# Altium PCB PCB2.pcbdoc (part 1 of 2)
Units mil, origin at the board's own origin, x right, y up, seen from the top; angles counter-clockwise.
Board outline 7114.17 x 3886.41 mil, 4 copper layers (Top Layer, Inner1, Inner2, Bottom Layer); 197 components, 125 nets, 754 pads, 711 vias.
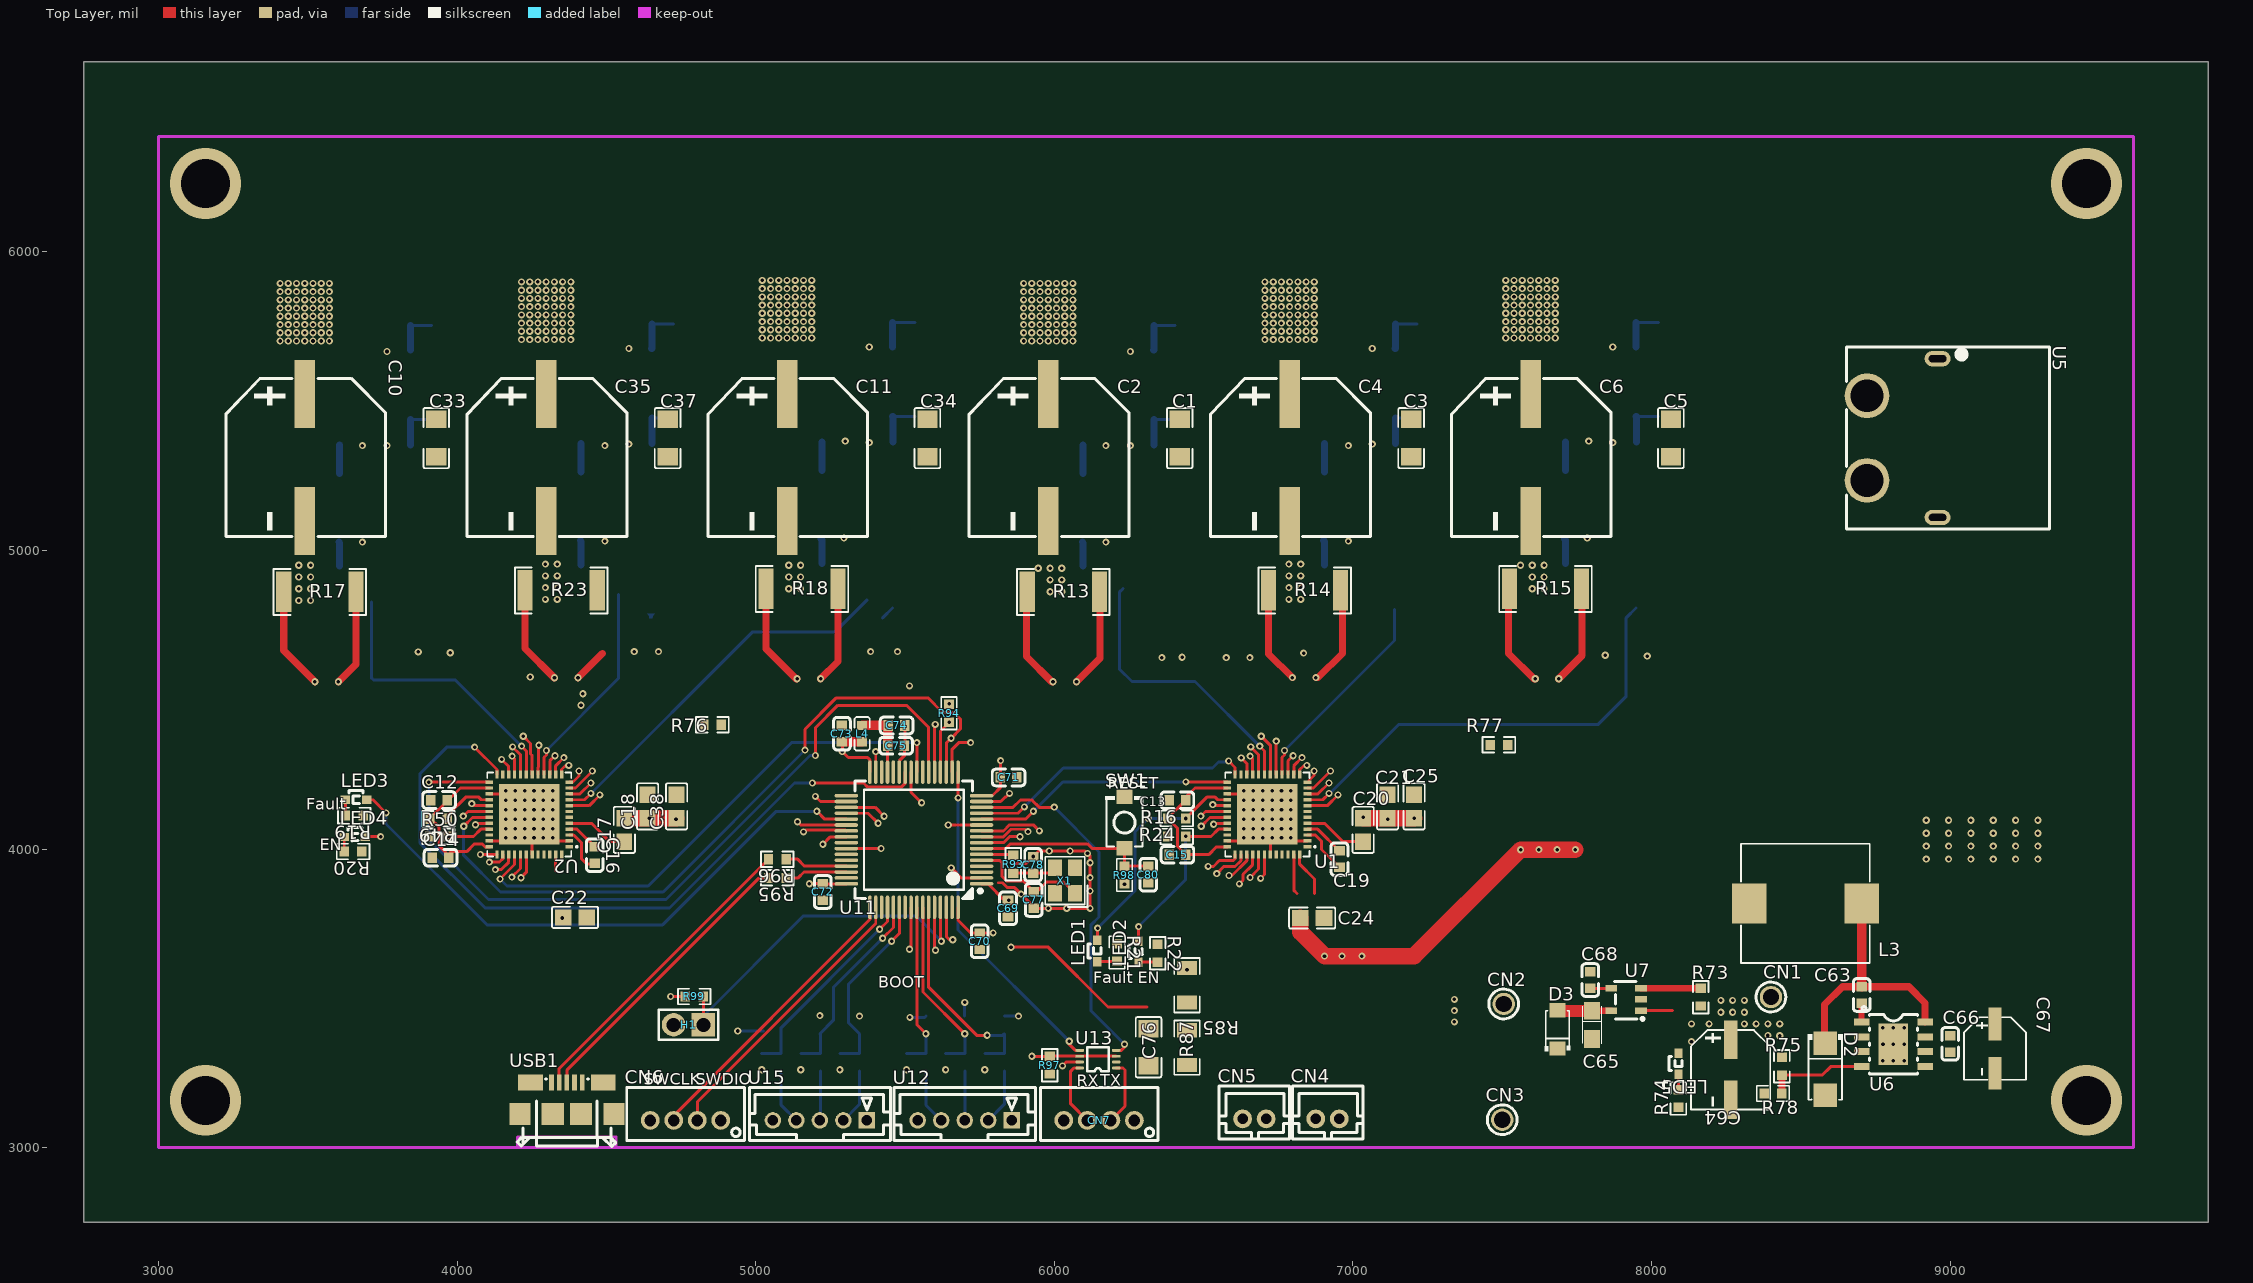
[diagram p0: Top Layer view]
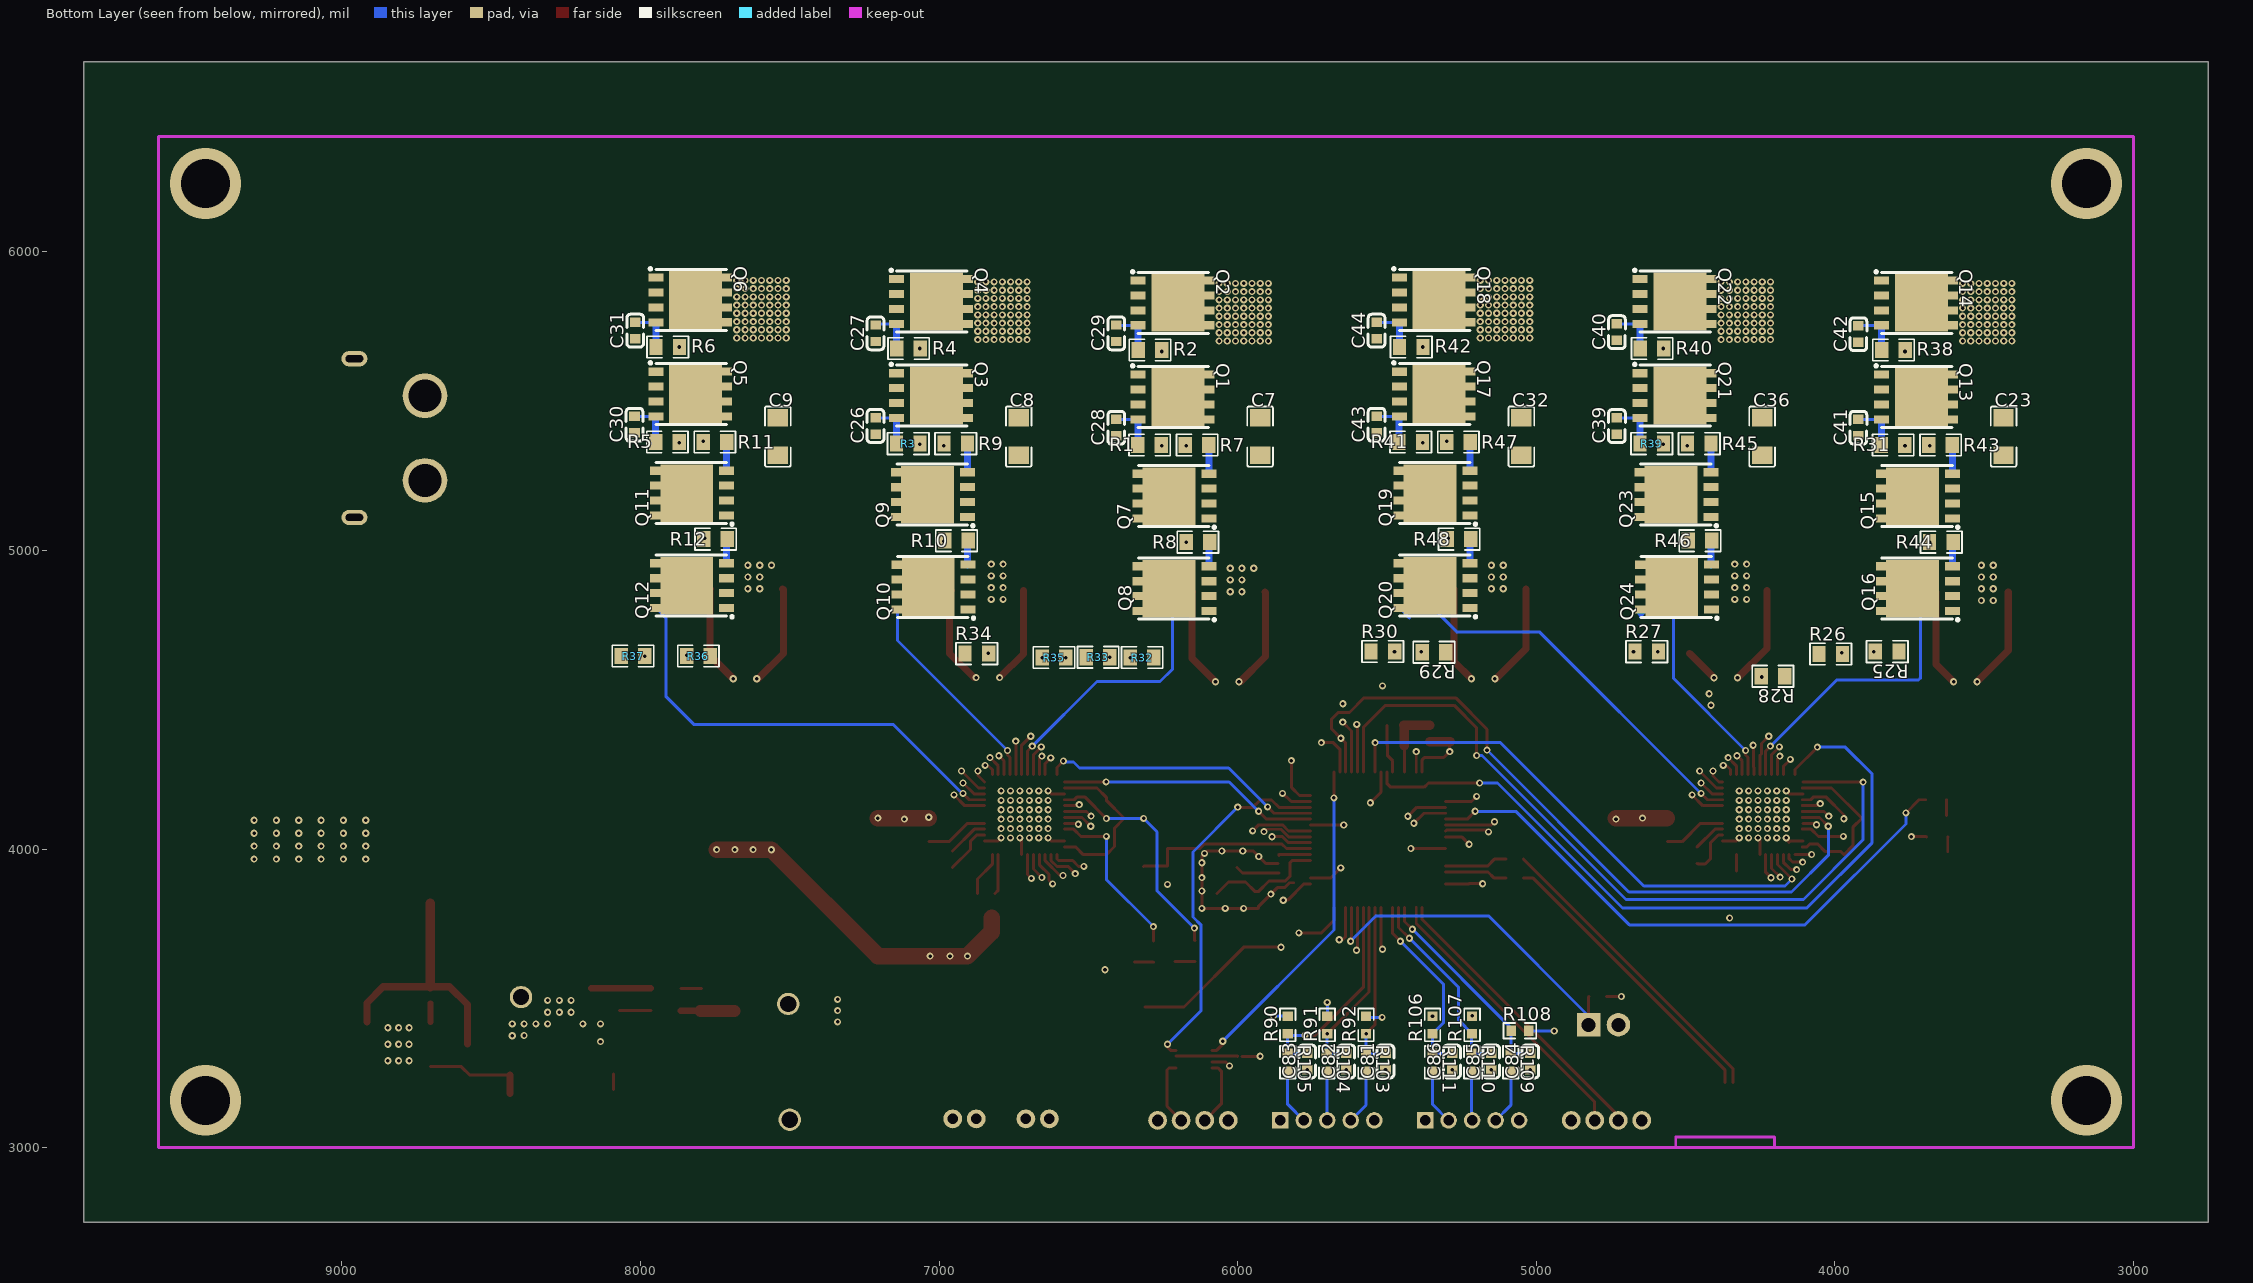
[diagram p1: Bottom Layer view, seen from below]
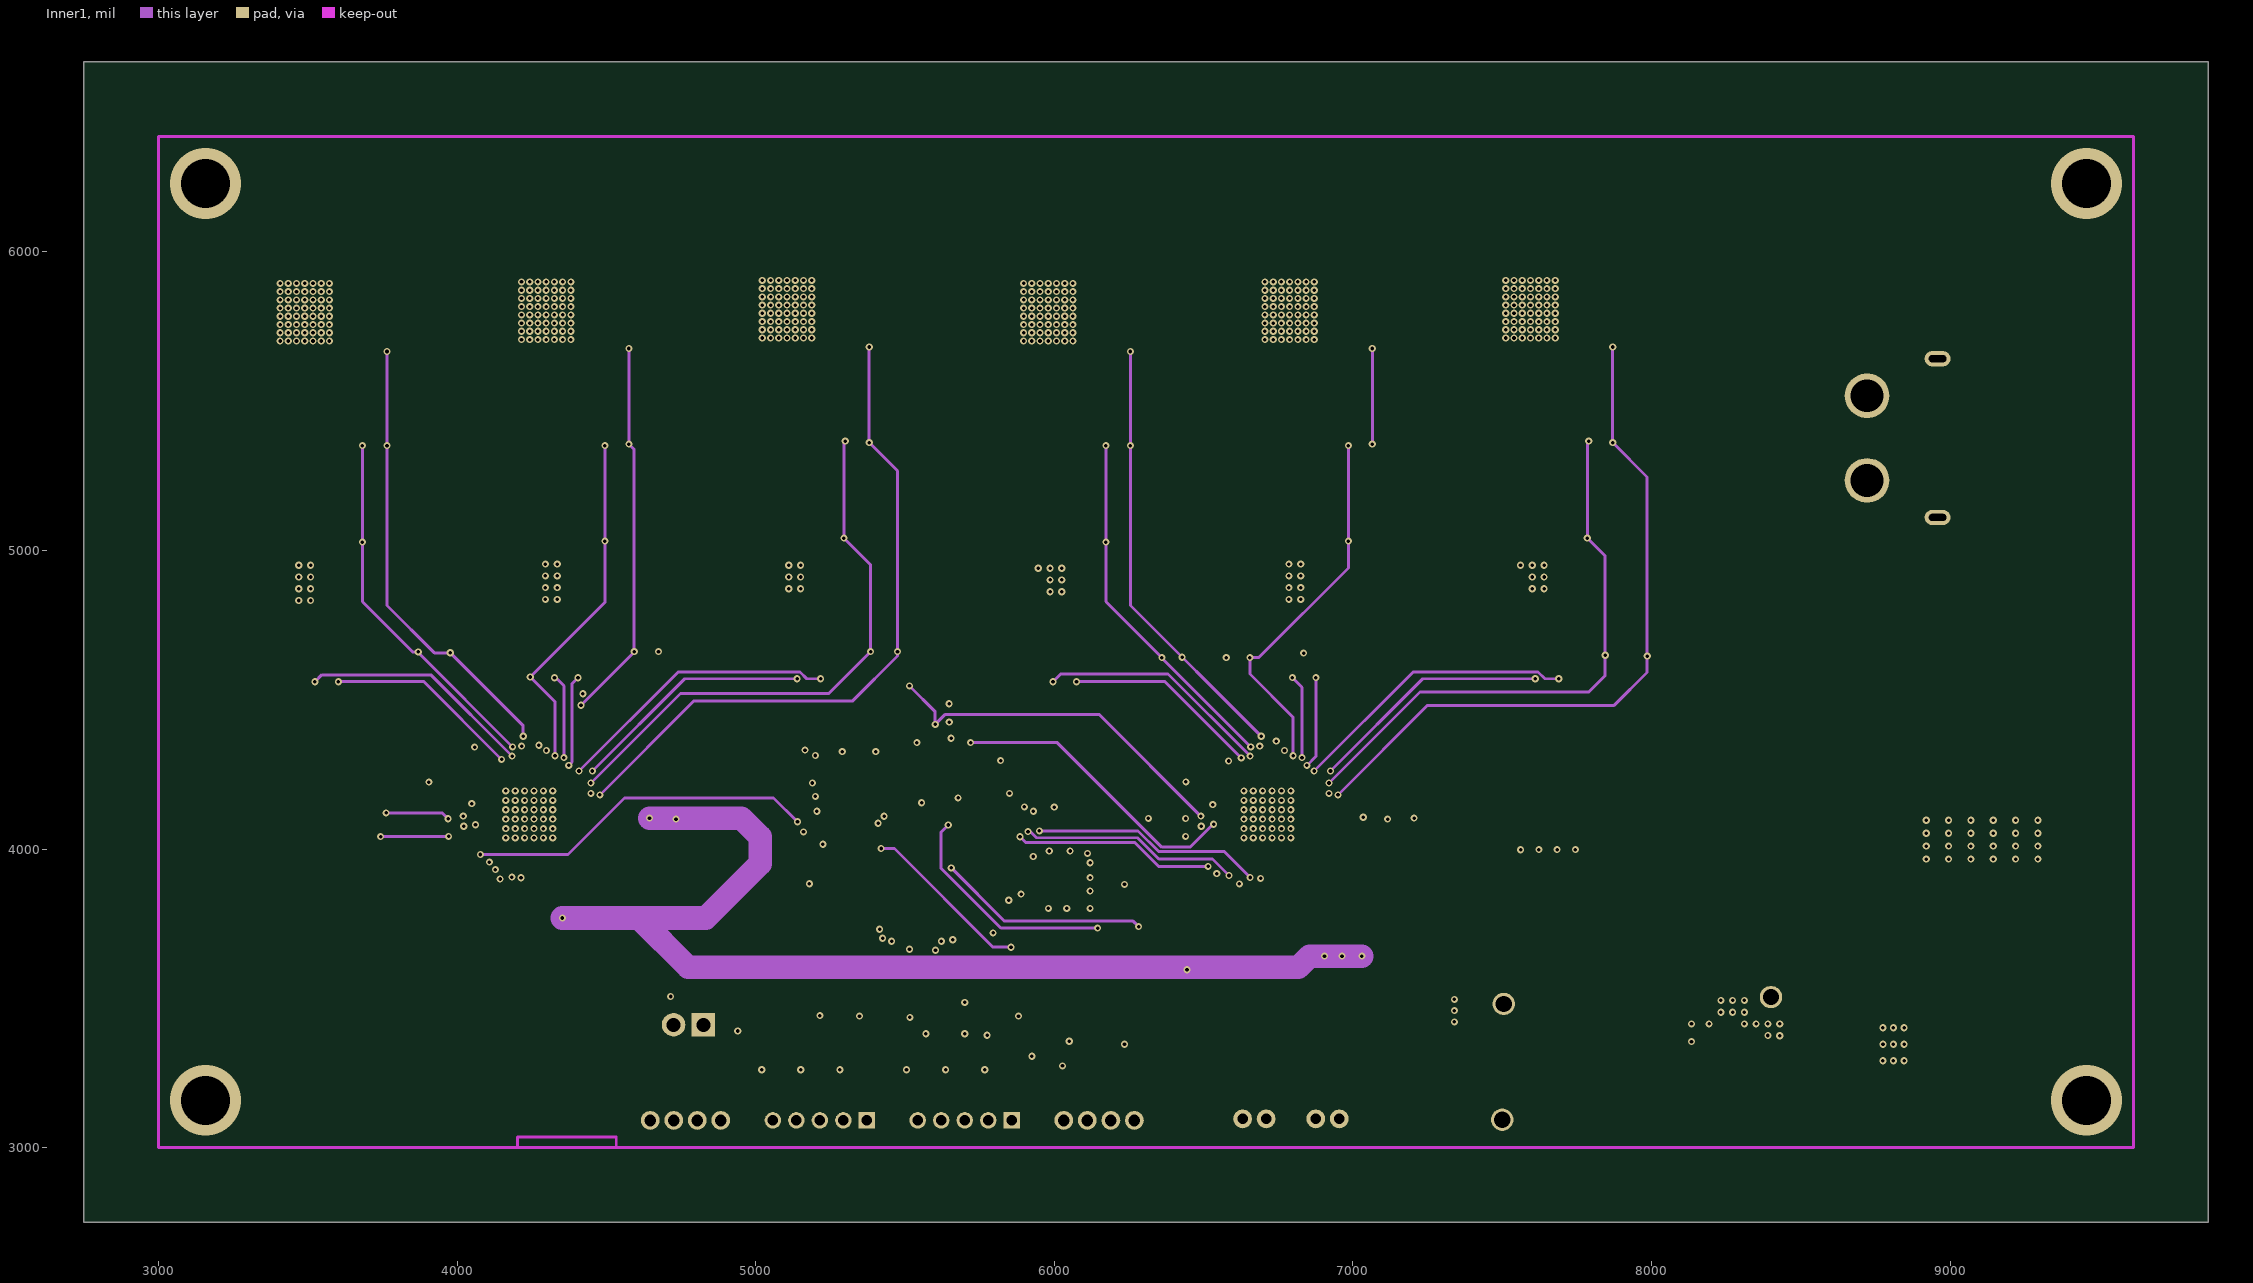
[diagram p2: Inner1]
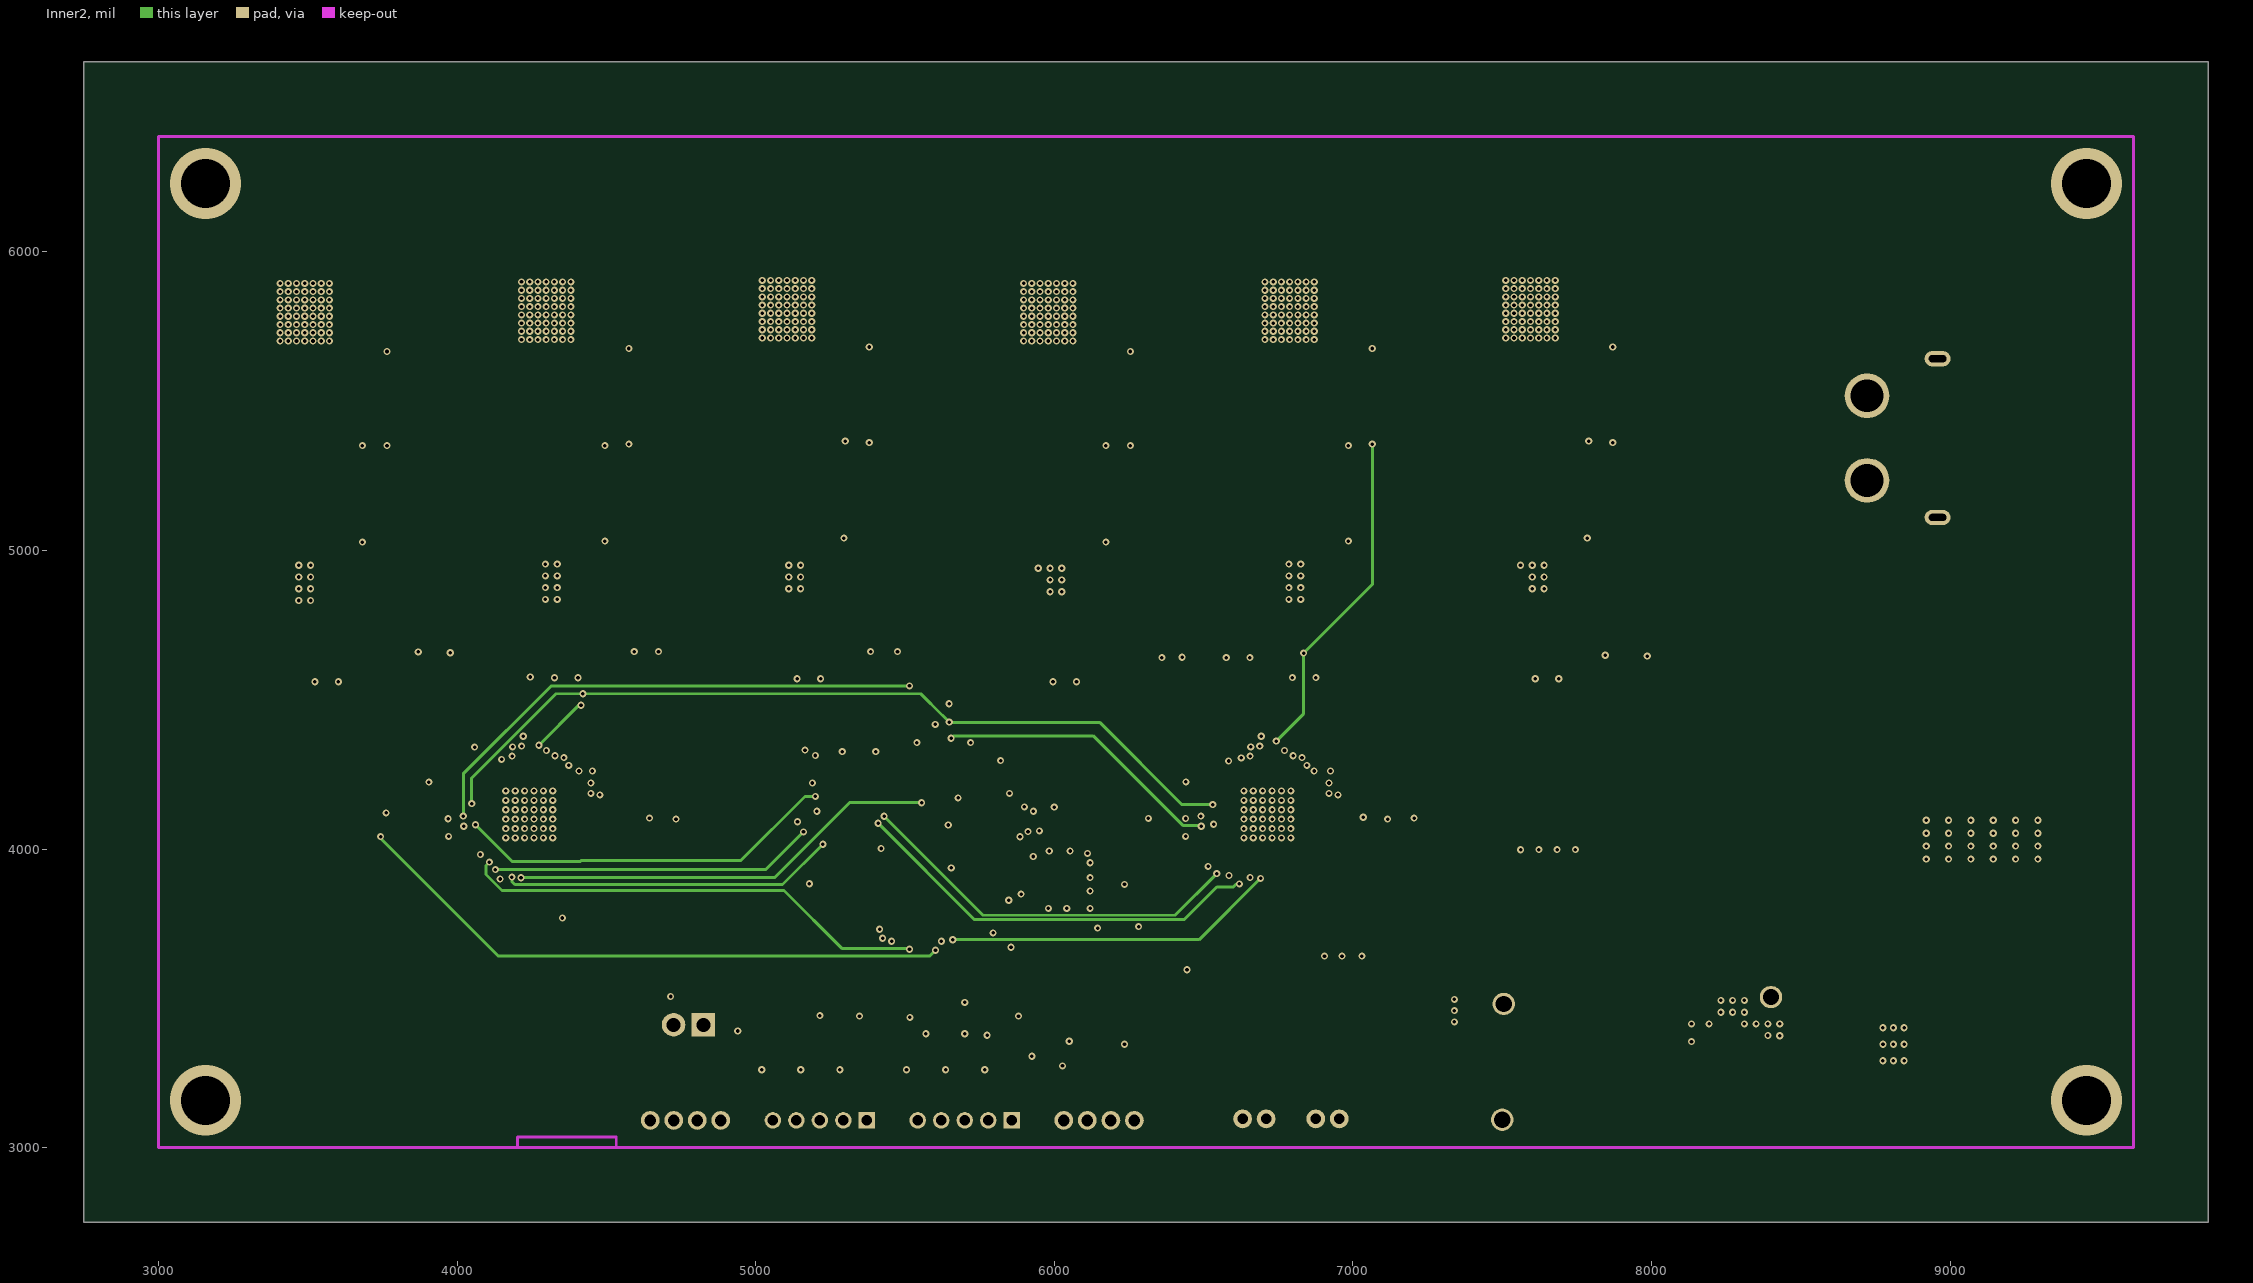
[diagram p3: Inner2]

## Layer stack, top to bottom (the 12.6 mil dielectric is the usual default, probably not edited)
Top Layer: signal copper (thickness not stored)
Dielectric: dielectric 12.6, FR-4, Dk 4.8
Inner1: signal copper (thickness not stored)
Dielectric: dielectric 12.6, FR-4, Dk 4.8
Inner2: signal copper (thickness not stored)
Dielectric: dielectric 12.6, FR-4, Dk 4.8
Bottom Layer: signal copper (thickness not stored)

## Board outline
9864.17,2750 2750,2750 2750,6636.41 9864.17,6636.41

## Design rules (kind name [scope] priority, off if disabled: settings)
BoardOutlineClearance copperThickness1oz [All] p0: genericclearance=10 ignorepadtopadclearanceinfootprint=FALSE except(0: Arc-SplitContinuation Track-SplitContinuation SMDPad-SplitContinuation THPad-SplitContinuation Via-SplitContinuation Fill-SplitContinuation Poly-SplitContinuation Region-SplitContinuation Text-SplitContinuation; 6: Track-CutoutEdge SMDPad-CutoutEdge THPad-CutoutEdge Via-CutoutEdge Region-CutoutEdge; 11.8: Track-OutlineEdge SMDPad-OutlineEdge THPad-OutlineEdge Via-OutlineEdge Fill-OutlineEdge Region-OutlineEdge Poly-OutlineEdge Text-OutlineEdge Fill-CutoutEdge)
BoardOutlineClearance copperThickness2oz [All] p0: genericclearance=10 ignorepadtopadclearanceinfootprint=FALSE except(0: Arc-SplitContinuation Track-SplitContinuation SMDPad-SplitContinuation THPad-SplitContinuation Via-SplitContinuation Fill-SplitContinuation Poly-SplitContinuation Region-SplitContinuation Text-SplitContinuation; 6: Track-CutoutEdge SMDPad-CutoutEdge THPad-CutoutEdge Via-CutoutEdge Region-CutoutEdge; 11.8: Track-OutlineEdge SMDPad-OutlineEdge THPad-OutlineEdge Via-OutlineEdge Fill-OutlineEdge Region-OutlineEdge Poly-OutlineEdge Text-OutlineEdge Fill-CutoutEdge)
Clearance copperThickness1oz [(InNet('VM') OR InNet('PGND') OR InNet('$1I2936\C_H') OR InNet('$1I2936\A_H') OR InNet('M1_C') OR InNet('M1_A') OR InNet('M1_B') OR InNet('$1I2936\GH_C') OR InNet('$1I2936\GH_B') OR InNet('$1I2936\GH_A') OR InNet('$1I2936\GL_C') OR InNet('$1I2936\GL_B') OR InNet('$1I2936\GL_A') OR InNet('PA0') OR InNet('AGND') OR InNet('PA1') OR InNet('$1I2936\DVDD') OR InNet('5V') OR InNet('$1I2936\B_H') OR InNet('MISO') OR InNet('MOSI') OR InNet('SCK') OR InNet('PA4') OR InNet('PB13') OR InNet('PB14') OR InNet('$1I3034\C_H') OR InNet('$1I3034\B_H') OR InNet('$1I3034\A_H') OR InNet('PC4') OR InNet('PC0') OR InNet('$1I3034\DVDD') OR InNet('$1N561') OR InNet('PH') OR InNet('3.3V') OR InNet('$1N2428') OR InNet('NRST') OR InNet('M2_C') OR InNet('M2_B') OR InNet('M2_A') OR InNet('$1I3034\GH_C') OR InNet('$1I3034\GH_B') OR InNet('$1I3034\GH_A') OR InNet('$1I3034\GL_C') OR InNet('$1I3034\GL_B') OR InNet('$1I3034\GL_A') OR InNet('$1N2597') OR InNet('$1N551') OR InNet('PB4') OR InNet('PB5') OR InNet('PB6') OR InNet('PB7') OR InNet('PB8') OR InNet('PB9') OR InNet('PB12') OR InNet('PC6') OR InNet('PB3') OR InNet('PC7') OR InNet('PB0') OR InNet('PC8') OR InNet('PB1') OR InNet('UART_RX') OR InNet('UART_TX') OR InNet('PA13') OR InNet('PA14') OR InNet('PC12') OR InNet('PC11') OR InNet('PC10') OR InNet('PC2') OR InNet('B2') OR InNet('B1') OR InNet('VDDA') OR InNet('PC1') OR InNet('$1N72792') OR InNet('$1N72949') OR InNet('$1N72945') OR InNet('PB15') OR InNet('PC3') OR InNet('PC13') OR InNet('PB2') OR InNet('$1N77944') OR InNet('$1N77945') OR InNet('D+') OR InNet('D-') OR InNet('$1I2936\$1N44900') OR InNet('$1I2936\$1N44903') OR InNet('$1I2936\$1N44964') OR InNet('$1I2936\$1N44967') OR InNet('$1I2936\$1N44911') OR InNet('$1I2936\$1N44914') OR InNet('$1I2936\$1N44906') OR InNet('$1I2936\$1N44907') OR InNet('$1I2936\$1N44970') OR InNet('$1I2936\$1N44971') OR InNet('$1I2936\$1N44917') OR InNet('$1I2936\$1N44918') OR InNet('$1I2936\$1N44883') OR InNet('$1I2936\$1N44882') OR InNet('$1I2936\$1N44875') OR InNet('$1N87601') OR InNet('$1I3034\$1N44883') OR InNet('$1I3034\$1N44882') OR InNet('$1I3034\$1N44875') OR InNet('$1I3034\$1N44964') OR InNet('$1I3034\$1N44967') OR InNet('$1I3034\$1N44900') OR InNet('$1I3034\$1N44903') OR InNet('$1I3034\$1N44911') OR InNet('$1I3034\$1N44914') OR InNet('$1I2936\$1N44985') OR InNet('$1I2936\$1N44986') OR InNet('$1I3034\$1N44985') OR InNet('$1I3034\$1N44986') OR InNet('$1I3034\$1N44906') OR InNet('$1I3034\$1N44907') OR InNet('$1I3034\$1N44917') OR InNet('$1I3034\$1N44918') OR InNet('$1I3034\$1N44970') OR InNet('$1I3034\$1N44971') OR InNet('PA8') OR InNet('$1N97534') OR InNet('$1N97530') OR InNet('$1N97516') OR InNet('$1N98528') OR InNet('$1N98530') OR InNet('$1N98532'))] p1: gap=7 ignorepadtopadclearanceinfootprint=FALSE except(4: Track-Track; 6: Track-SMDPad SMDPad-SMDPad Track-THPad SMDPad-THPad THPad-THPad Track-Via SMDPad-Via THPad-Via Via-Via SMDPad-Fill THPad-Fill Via-Fill Fill-Fill Track-Region SMDPad-Region THPad-Region Via-Region Region-Region Track-Poly SMDPad-Poly THPad-Poly Via-Poly Fill-Poly Region-Poly Poly-Poly Track-Text SMDPad-Text THPad-Text Via-Text Fill-Text Region-Text Poly-Text Text-Text; 6.9: Track-Hole SMDPad-Hole THPad-Hole Via-Hole Fill-Hole Region-Hole Poly-Hole Text-Hole Sheet-Hole; 11.8: Track-Fill Fill-Region Track-Sheet SMDPad-Sheet THPad-Sheet Via-Sheet Fill-Sheet Region-Sheet Poly-Sheet Text-Sheet)
Clearance copperThickness2oz [All] p1: gap=7 ignorepadtopadclearanceinfootprint=FALSE except(6: Track-SMDPad SMDPad-SMDPad Track-THPad SMDPad-THPad THPad-THPad Track-Via SMDPad-Via THPad-Via Via-Via SMDPad-Fill THPad-Fill Via-Fill Fill-Fill Track-Region SMDPad-Region THPad-Region Via-Region Region-Region Track-Poly SMDPad-Poly THPad-Poly Via-Poly Fill-Poly Region-Poly Poly-Poly Track-Text SMDPad-Text THPad-Text Via-Text Fill-Text Region-Text Poly-Text Text-Text; 6.9: Track-Hole SMDPad-Hole THPad-Hole Via-Hole Fill-Hole Region-Hole Poly-Hole Text-Hole Sheet-Hole; 8: Track-Track; 11.8: Track-Fill Fill-Region Track-Sheet SMDPad-Sheet THPad-Sheet Via-Sheet Fill-Sheet Region-Sheet Poly-Sheet Text-Sheet)
DiffPairsRouting differentialPair [All] p1: maxuncoupledlength=10 minlimit=5.9843 maxlimit=5.9843 mostfreqgap=5.9843 toplayer_minwidth=5 toplayer_prefwidth=10 toplayer_maxwidth=100 bottomlayer_minwidth=5 bottomlayer_prefwidth=10 bottomlayer_maxwidth=100 midlayer1_minwidth=5 midlayer1_prefwidth=10 midlayer1_maxwidth=100 midlayer2_minwidth=5 midlayer2_prefwidth=10 midlayer2_maxwidth=100
PasteMaskExpansion pasteMaskExpansion [All] p1: expansion=0
PlaneConnect innerPlane [All] p1: planeconnectstyle=Relief reliefexpansion=20 reliefentries=4 reliefconductorwidth=10 reliefairgap=10
PolygonConnect copperRegion [All] p1: connectstyle=Direct reliefentries=4 reliefconductorwidth=10 polygonreliefangle="90 Angle" airgapwidth=10
RoutingVias viaSize [All] p1: viastyle="Through Hole" holewidth=12.0078 minholewidth=11.811 maxholewidth=248.0314 width=24.0158 minwidth=19.685 maxwidth=393.7008
SolderMaskExpansion solderMaskExpansion [All] p1: useseparateexpansions=TRUE expansion=2.0079 expansionbottom=2.0079
Width copperThickness1oz [All] p1: maxlimit=100 minlimit=5 preferedwidth=10
Width copperThickness2oz [All] p1: maxlimit=100 minlimit=8 preferedwidth=10

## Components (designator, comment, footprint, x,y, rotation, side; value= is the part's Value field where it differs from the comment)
C1 "CL31B104KBCNNNC" C1206 6420,5376.36 r90 top
C2 "VMML1652A221MV" CAP-SMD_BD12.5-L13.5-W13.5-FD-1 5980,5311.41 r270 top
C3 "CL31B104KBCNNNC" C1206 7195,5376.36 r90 top
C4 "VMML1652A221MV" CAP-SMD_BD12.5-L13.5-W13.5-FD-1 6788.4,5311.41 r270 top
C5 "CL31B104KBCNNNC" C1206 8065,5376.36 r90 top
C6 "VMML1652A221MV" CAP-SMD_BD12.5-L13.5-W13.5-FD-1 7595,5311.41 r270 top
C7 "CC1206KRX7R0BB103" C1206 5925,5381.41 r90 bottom
C8 "CC1206KRX7R0BB103" C1206 6733.4,5381.41 r90 bottom
C9 "CC1206KRX7R0BB103" C1206 7540,5381.41 r90 bottom
C10 "VMML1652A221MV" CAP-SMD_BD12.5-L13.5-W13.5-FD-1 3490.42,5311.41 r270 top
C11 "VMML1652A221MV" CAP-SMD_BD12.5-L13.5-W13.5-FD-1 5105.18,5311.41 r270 top
C12 "CL10B104KC8NNNC" C0603 3939.69,4164.09 r0 top
C13 "CL10B104KC8NNNC" C0603 6412.28,4163.37 r0 top
C14 "CL10B104KC8NNNC" C0603 3944.69,3971.41 r0 top
C15 "CL10B104KC8NNNC" C0603 6412.28,3981.41 r0 top
C16 "AC0603KRX7R0BB473" C0603 4461.07,3979.83 r270 top
C17 "GCM21BC72A105KE36L" C0805 4560,4064.22 r90 top
C18 "CL21B104KCFNNNE" C0805 4637.98,4142.96 r90 top
C19 "AC0603KRX7R0BB473" C0603 6955,3966.41 r270 top
C20 "GCM21BC72A105KE36L" C0805 7034.37,4064.22 r90 top
C21 "CL21B104KCFNNNE" C0805 7116.26,4142.96 r90 top
C22 "GCM21BR72A104KA37L" C0805 4395,3771.41 r0 top
C23 "CC1206KRX7R0BB103" C1206 3435.18,5381.41 r90 bottom
C24 "GCM21BR72A104KA37L" C0805 6863.71,3769.2 r0 top
C25 "CL21A106KAYNNNE_C15850" C0805 7205,4142.96 r90 top
C26 "CL10C101JB8NNNC" C0603 7212.78,5417.42 r90 bottom
C27 "CL10C101JB8NNNC" C0603 7212.78,5727.42 r90 bottom
C28 "CL10C101JB8NNNC" C0603 6406.38,5411.41 r90 bottom
C29 "CL10C101JB8NNNC" C0603 6406.38,5727.42 r90 bottom
C30 "CL10C101JB8NNNC" C0603 8020,5421.41 r90 bottom
C31 "CL10C101JB8NNNC" C0603 8017.41,5736.41 r90 bottom
C32 "CC1206KRX7R0BB103" C1206 5050,5381.41 r90 bottom
C33 "CL31B104KBCNNNC" C1206 3930.18,5376.36 r90 top
C34 "CL31B104KBCNNNC" C1206 5575.18,5376.36 r90 top
C35 "VMML1652A221MV" CAP-SMD_BD12.5-L13.5-W13.5-FD-1 4298.58,5311.41 r270 top
C36 "CC1206KRX7R0BB103" C1206 4243.58,5381.41 r90 bottom
C37 "CL31B104KBCNNNC" C1206 4705.18,5376.36 r90 top
C38 "CL21A106KAYNNNE_C15850" C0805 4735,4142.96 r90 top
C39 "CL10C101JB8NNNC" C0603 4730,5417.01 r90 bottom
C40 "CL10C101JB8NNNC" C0603 4730,5731.41 r90 bottom
C41 "CL10C101JB8NNNC" C0603 3921.23,5411.41 r90 bottom
C42 "CL10C101JB8NNNC" C0603 3921.23,5724.57 r90 bottom
C43 "CL10C101JB8NNNC" C0603 5535,5421.41 r90 bottom
C44 "CL10C101JB8NNNC" C0603 5534.89,5736.41 r90 bottom
C63 "CC0603KRX7R9BB103" C0603 8703.7,3511.41 r270 top
C64 "VZH101M1ETR-0607" CAP-SMD_BD6.3-L6.6-W6.6-LS7.2-R-RD 8265,3261.41 r90 top
C65 "TAJA225K016RNJ" CASE-A_3216 7800,3411.41 r270 top
C66 "CC0603KRX7R9BB104" C0603 9000,3347.79 r90 top
C67 "JVJ50v10M5x5" CAP-SMD_BD5.0-L5.3-W5.3-LS6.0-FD 9150,3332.04 r270 top
C68 "CC0603JRNPO9BN471" C0603 7795,3561.41 r270 top
C69 "CC0603KRX7R9BB104" C0603 5845,3801.41 r90 top
C70 "CC0603KRX7R9BB104" C0603 5750,3691.41 r90 top
C71 "CC0603KRX7R9BB104" C0603 5846.9,4239.88 r180 top
C72 "CC0603KRX7R9BB104" C0603 5225,3856.41 r90 top
C73 "CC0603KRX7R9BB104" C0603 5288.8,4386.53 r270 top
C74 "CL10A106KP8NNNC" C0603 5471.69,4413.97 r180 top
C75 "CC0603KRX7R9BB104" C0603 5470,4346.41 r180 top
C76 "GRM31C5C1H104JA01L" C1206 6315.53,3336.35 r90 top
C77 "CC0603FRNPO9BN200" C0603 5930.76,3829.73 r270 top
C78 "CC0603FRNPO9BN200" C0603 5928.95,3947.16 r90 top
C80 "CC0603KRX7R9BB104" C0603 6315,3914.32 r90 top
C81 "CAP_0603" C0603 5505,3288.51 r90 bottom
C82 "CAP_0603" C0603 5636.05,3288.51 r90 bottom
C83 "CAP_0603" C0603 5767.1,3288.51 r90 bottom
C84 "CAP_0603" C0603 5020,3288.51 r90 bottom
C85 "CAP_0603" C0603 5151.05,3288.51 r90 bottom
C86 "CAP_0603" C0603 5282.1,3288.51 r90 bottom
CN1 "RH-5001" TEST-TH_BD2.54-P1.4_BLACK 8400,3504.44 r0 top
CN2 "RH-5001" TEST-TH_BD2.54-P1.4_BLACK 7505,3481.41 r0 top
CN3 "RH-5001" TEST-TH_BD2.54-P1.4_BLACK 7500,3093.77 r0 top
CN4 "B2B-PH-K-S(LF)(SN)" CONN-TH_B2B-PH-K-S 6915,3096.41 r0 top
CN5 "B2B-PH-K-S(LF)(SN)" CONN-TH_B2B-PH-K-S 6670,3096.41 r0 top
CN6 "B4B-PH-K-S(LF)(SN)" CONN-TH_B4B-PH-K-S 4765,3091.41 r0 top
CN7 "B4B-PH-K-S(LF)(SN)" CONN-TH_B4B-PH-K-S 6150,3091.41 r0 top
D2 "SS56_C65009" SMA_L4.3-W2.6-LS5.2-RD 8581.61,3263.02 r270 top
D3 "SMF3.3" SOD-123FL_L3.0-W1.9-LS3.7-FD 7685,3396.41 r270 top
H1 "PZ254V-11-02P" HDR-TH_2P-P2.54-V-M 4775,3411.41 r180 top
L3 "SLO1040H150MTT" IND-SMD_L10.8-W10.0_SLO1040H 8515.6,3818.21 r180 top
L4 "BLM18KG121TN1D" L0603 5356.35,4386.38 r90 top
LED1 "LTST-S270KGKT" LED-SMD_L1.7-W0.6-RD 6143.6,3658.61 r90 top
LED2 "LTST-S270KGKT" LED-SMD_L1.7-W0.6-RD 6282.12,3656.45 r90 top
LED3 "LTST-S270KGKT" LED-SMD_L1.7-W0.6-RD 3661.46,4165.21 r0 top
LED4 "LTST-S270KGKT" LED-SMD_L1.7-W0.6-RD 3657.44,4040.21 r0 top
LED5 "LTST-S270KGKT" LED-SMD_L1.7-W0.6-RD 8090,3281.41 r90 top
Q1 "CSD18540Q5B" VSON-CLIP-8_L5.0-W6.0-P1.27-BL 6215.52,5513.93 r270 bottom
Q2 "CSD18540Q5B" VSON-CLIP-8_L5.0-W6.0-P1.27-BL 6215.52,5828.93 r270 bottom
Q3 "CSD18540Q5B" VSON-CLIP-8_L5.0-W6.0-P1.27-BL 7023.93,5518.8 r270 bottom
Q4 "CSD18540Q5B" VSON-CLIP-8_L5.0-W6.0-P1.27-BL 7023.93,5833.8 r270 bottom
Q5 "CSD18540Q5B" VSON-CLIP-8_L5.0-W6.0-P1.27-BL 7830.52,5523.93 r270 bottom
Q6 "CSD18540Q5B" VSON-CLIP-8_L5.0-W6.0-P1.27-BL 7830.52,5838.93 r270 bottom
Q7 "CSD18540Q5B" VSON-CLIP-8_L5.0-W6.0-P1.27-BL 6214.82,5182.25 r90 bottom
Q8 "CSD18540Q5B" VSON-CLIP-8_L5.0-W6.0-P1.27-BL 6214.82,4872.25 r90 bottom
Q9 "CSD18540Q5B" VSON-CLIP-8_L5.0-W6.0-P1.27-BL 7023.23,5187.12 r90 bottom
Q10 "CSD18540Q5B" VSON-CLIP-8_L5.0-W6.0-P1.27-BL 7021.04,4877.58 r90 bottom
Q11 "CSD18540Q5B" VSON-CLIP-8_L5.0-W6.0-P1.27-BL 7829.82,5192.25 r90 bottom
Q12 "CSD18540Q5B" VSON-CLIP-8_L5.0-W6.0-P1.27-BL 7829.82,4882.25 r90 bottom
Q13 "CSD18540Q5B" VSON-CLIP-8_L5.0-W6.0-P1.27-BL 3725.7,5513.93 r270 bottom
Q14 "CSD18540Q5B" VSON-CLIP-8_L5.0-W6.0-P1.27-BL 3725.7,5828.93 r270 bottom
Q15 "CSD18540Q5B" VSON-CLIP-8_L5.0-W6.0-P1.27-BL 3725,5182.25 r90 bottom
Q16 "CSD18540Q5B" VSON-CLIP-8_L5.0-W6.0-P1.27-BL 3725,4872.25 r90 bottom
Q17 "CSD18540Q5B" VSON-CLIP-8_L5.0-W6.0-P1.27-BL 5340.7,5523.93 r270 bottom
Q18 "CSD18540Q5B" VSON-CLIP-8_L5.0-W6.0-P1.27-BL 5340.7,5838.93 r270 bottom
Q19 "CSD18540Q5B" VSON-CLIP-8_L5.0-W6.0-P1.27-BL 5340,5192.25 r90 bottom
Q20 "CSD18540Q5B" VSON-CLIP-8_L5.0-W6.0-P1.27-BL 5340,4882.25 r90 bottom
Q21 "CSD18540Q5B" VSON-CLIP-8_L5.0-W6.0-P1.27-BL 4534.1,5518.8 r270 bottom
Q22 "CSD18540Q5B" VSON-CLIP-8_L5.0-W6.0-P1.27-BL 4534.1,5833.8 r270 bottom
Q23 "CSD18540Q5B" VSON-CLIP-8_L5.0-W6.0-P1.27-BL 4533.4,5187.12 r90 bottom
Q24 "CSD18540Q5B" VSON-CLIP-8_L5.0-W6.0-P1.27-BL 4531.21,4877.58 r90 bottom
R1 "0805W8F220JT5E" R0805 6295,5353.07 r180 bottom
R2 "0805W8F220JT5E" R0805 6293.74,5671.41 r0 bottom
R3 "0805W8F220JT5E" R0805 7103.4,5357.94 r180 bottom
R4 "0805W8F220JT5E" R0805 7102.14,5676.28 r0 bottom
R5 "0805W8F220JT5E" R0805 7910,5363.07 r180 bottom
R6 "0805W8F220JT5E" R0805 7908.74,5681.41 r0 bottom
R7 "0805W8F220JT5E" R0805 6135.83,5353.07 r0 bottom
R8 "0805W8F220JT5E" R0805 6133.38,5028.07 r180 bottom
R9 "0805W8F220JT5E" R0805 6944.23,5357.94 r0 bottom
R10 "0805W8F220JT5E" R0805 6941.78,5032.94 r180 bottom
R11 "0805W8F220JT5E" R0805 7750.83,5363.07 r0 bottom
R12 "0805W8F220JT5E" R0805 7748.38,5038.07 r180 bottom
R13 "HoYLR2512-2W-5mR-1%" R2512 6030,4861.41 r180 top
R14 "HoYLR2512-2W-5mR-1%" R2512 6838.4,4866.28 r180 top
R15 "HoYLR2512-2W-5mR-1%" R2512 7645,4871.41 r180 top
R16 "0603WAF1001T5E" R0603 6410.18,4102.48 r180 top
R17 "HoYLR2512-2W-5mR-1%" R2512 3540.18,4861.41 r180 top
R18 "HoYLR2512-2W-5mR-1%" R2512 5155.18,4871.41 r180 top
R19 "0603WAF3300T5E" R0603 3655.78,4112.17 r180 top
R20 "0603WAF3300T5E" R0603 3651.76,3992.17 r180 top
R21 "0603WAF3300T5E" R0603 6209.89,3653.61 r270 top
R22 "0603WAF3300T5E" R0603 6346.17,3651.45 r270 top
R23 "HoYLR2512-2W-5mR-1%" R2512 4348.58,4866.28 r180 top
R24 "0603WAF1001T5E" R0603 6410.18,4042.3 r0 top
R25 "0805W8F1002T5E_C17414" R0805 3825,4661.41 r0 bottom
R26 "0805W8F1002T5E_C17414" R0805 4013.91,4653.39 r180 bottom
R27 "0805W8F1002T5E_C17414" R0805 4630,4661.41 r180 bottom
R28 "0805W8F1002T5E_C17414" R0805 4207.65,4578.91 r0 bottom
R29 "0805W8F1002T5E_C17414" R0805 5342.65,4659.37 r0 bottom
R30 "0805W8F1002T5E_C17414" R0805 5513.9,4661.47 r180 bottom
R31 "0805W8F220JT5E" R0805 3805.18,5353.07 r180 bottom
R32 "0805W8F1002T5E_C17414" R0805 6320,4641.41 r0 bottom
R33 "0805W8F1002T5E_C17414" R0805 6467.34,4642.44 r180 bottom
R34 "0805W8F1002T5E_C17414" R0805 6873.6,4654.54 r180 bottom
R35 "0805W8F1002T5E_C17414" R0805 6615,4641.41 r0 bottom
R36 "0805W8F1002T5E_C17414" R0805 7806.08,4646.41 r0 bottom
R37 "0805W8F1002T5E_C17414" R0805 8025,4646.41 r180 bottom
R38 "0805W8F220JT5E" R0805 3803.92,5671.41 r0 bottom
R39 "0805W8F220JT5E" R0805 4613.58,5357.94 r180 bottom
R40 "0805W8F220JT5E" R0805 4612.32,5676.28 r0 bottom
R41 "0805W8F220JT5E" R0805 5420.18,5363.07 r180 bottom
R42 "0805W8F220JT5E" R0805 5418.92,5681.41 r0 bottom
R43 "0805W8F220JT5E" R0805 3646.01,5353.07 r0 bottom
R44 "0805W8F220JT5E" R0805 3643.55,5028.07 r180 bottom
R45 "0805W8F220JT5E" R0805 4454.41,5357.94 r0 bottom
R46 "0805W8F220JT5E" R0805 4451.96,5032.94 r180 bottom
R47 "0805W8F220JT5E" R0805 5261.01,5363.07 r0 bottom
R48 "0805W8F220JT5E" R0805 5258.55,5038.07 r180 bottom
R49 "0603WAF1001T5E" R0603 3937.59,4101.41 r180 top
R50 "0603WAF1001T5E" R0603 3937.59,4042.3 r0 top
R73 "0603WAF1002T5E" R0603 8165,3504.16 r270 top
R74 "0603WAF3300T5E" R0603 8090,3164.72 r90 top
R75 "0603WAF1002T5E" R0603 8436.66,3272.42 r90 top
R76 "RC0603FR-070RL" R0603 4855,4416.41 r180 top
R77 "RC0603FR-070RL" R0603 7488.82,4348.98 r180 top
R78 "0603WAF3241T5E" R0603 8407,3181.41 r0 top
R85 "1206W4F1203T5E" R1206 6444.27,3543.93 r90 top
R87 "1206W4F1002T5E" R1206 6444.27,3335.37 r90 top
R90 "0603WAF1002T5E" R0603 5832.63,3411.12 r90 bottom
R91 "0603WAF1002T5E" R0603 5700,3411.12 r90 bottom
R92 "0603WAF1002T5E" R0603 5570.26,3411.12 r90 bottom
R93 "0603WAF1001T5E" R0603 5862.27,3949.26 r90 top
R94 "0603WAF1002T5E" R0603 5647.53,4454.77 r90 top
R95 "0603WAF220JT5E" R0603 5072.53,3903.71 r180 top
R96 "0603WAF220JT5E" R0603 5072.53,3966.01 r180 top
R97 "0603WAF1002T5E" R0603 5985,3276.41 r90 top
R98 "0603WAF1002T5E" R0603 6235,3913.16 r270 top
R99 "0603WAF1002T5E" R0603 4794.32,3506.41 r180 top
R103 "Res_0603" R0603 5570.53,3286.41 r270 bottom
R104 "Res_0603" R0603 5701.58,3286.41 r270 bottom
R105 "Res_0603" R0603 5832.63,3286.41 r270 bottom
R106 "0603WAF1002T5E" R0603 5347.63,3411.12 r90 bottom
R107 "0603WAF1002T5E" R0603 5215,3411.12 r90 bottom
R108 "0603WAF1002T5E" R0603 5055,3391.41 r180 bottom
R109 "Res_0603" R0603 5085.53,3286.41 r270 bottom
R110 "Res_0603" R0603 5216.58,3286.41 r270 bottom
R111 "Res_0603" R0603 5347.63,3286.41 r270 bottom
SW1 "TS-1088-AR02016" SW-SMD_L3.9-W3.0-P4.45 6235,4088.71 r90 top
U1 "DRV8323RSRGZR" VQFN-48_L7.0-W7.0-P0.50-TL-EP5.1 6713.52,4116 r180 top
U2 "DRV8323RSRGZR" VQFN-48_L7.0-W7.0-P0.50-TL-EP5.1 4241.74,4116 r180 top
U5 "XT60PW-F" TH_2P-XT60PW-F 8840,5376.41 r270 top
U6 "TPS5430DDAR" ESOP-8_L4.9-W3.9-P1.27-LS6.0-TL-EP 8810,3346.41 r0 top
U7 "MIC5219-3.3YM5-TR" SOT-23-5_L3.0-W1.7-P0.95-LS2.8-TL 7915,3496.41 r180 top
U11 "STM32G474RET6" LQFP-64_L10.0-W10.0-P0.50-LS12.0-BL 5530,4031.41 r90 top
U12 "B5B-PH-K-S(LF)(SN)" CONN-TH_B5B-PH-K-S-LF-SN 5700,3091.41 r0 top
U13 "TXB0102DCUR" VSSOP-8_L2.4-W2.1-P0.50-LS3.2-BR 6146.34,3296.41 r0 top
U15 "B5B-PH-K-S(LF)(SN)" CONN-TH_B5B-PH-K-S-LF-SN 5215,3091.41 r0 top
USB1 "ZX62-AB-5PA(31)" MICRO-USB-SMD_ZX62-AB-5PA 4367.66,3165.35 r0 top
X1 "X32258MSB4SI" CRYSTAL-SMD_4P-L3.2-W2.5-BL 6035.76,3894.73 r90 top

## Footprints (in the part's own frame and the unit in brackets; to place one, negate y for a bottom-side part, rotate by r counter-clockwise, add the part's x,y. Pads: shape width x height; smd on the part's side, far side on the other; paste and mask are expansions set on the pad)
C0603 [mm]
  rect 0.8x0.9 smd: 1(-0.7,0) 2(0.7,0)
  silkscreen extent -1.39,-0.71 1.39,0.71
C0805 [mm]
  rect 1.41x1.35 smd: 1(-1,0) 2(1,0)
  silkscreen extent -1.96,-0.9 1.96,0.9
C1206 [mm]
  rect 1.485x1.728 smd: 1(-1.593,0) 2(1.593,0)
  silkscreen extent -2.56,-1.09 2.56,1.09
CAP-SMD_BD5.0-L5.3-W5.3-LS6.0-FD [mm]
  rect 2.8x1.1 smd: 1(-2.1,0) 2(2.1,0)
  silkscreen extent -2.66,-2.62 2.66,2.65
CAP-SMD_BD6.3-L6.6-W6.6-LS7.2-R-RD [mm]
  rect 3.26x1.15 smd: 1(2.555,0) 2(-2.555,0)
  silkscreen extent -3.39,-3.38 3.36,3.38
CAP-SMD_BD12.5-L13.5-W13.5-FD-1 [mm]
  rect 5.8x1.75 smd: 1(-5.4,0) 2(5.4,0)
  silkscreen extent -6.73,-6.73 6.73,6.86
CASE-A_3216 [mil]
  rect 59.05x53.5 smd: 1(-47.24,0) 2(47.24,0)
  silkscreen extent -63,-32 63,32
CONN-TH_B2B-PH-K-S [mm]
  round 1.6 hole 0.9: 1(1,0) 2(-1,0)
  silkscreen extent -3,-1.7 3,2.8
CONN-TH_B4B-PH-K-S [mm]
  round 1.6 hole 1: 1(3,0) 2(1,0) 3(-1,0) 4(-3,0)
  silkscreen extent -5,-1.7 5,2.8
CONN-TH_B5B-PH-K-S-LF-SN [mm]
  rect 1.4x1.4 hole 0.9: 1(4,0)
  round 1.4 hole 0.9: 2(2,0) 3(0,0) 4(-2,0) 5(-4,0)
  silkscreen extent -6,-1.7 6,2.8
CRYSTAL-SMD_4P-L3.2-W2.5-BL [mm]
  rect 1.4x1.2 smd: 1(-1.1,-0.85) 2(1.1,-0.85) 3(1.1,0.85) 4(-1.1,0.85)
  silkscreen extent -2.26,-1.91 2.03,1.68
ESOP-8_L4.9-W3.9-P1.27-LS6.0-TL-EP [mm]
  rect 1.3x0.6 smd: 1(-2.7,1.905) 2(-2.7,0.635) 3(-2.7,-0.635) 4(-2.7,-1.905) 5(2.7,-1.905) 6(2.7,-0.635) 7(2.7,0.635) 8(2.7,1.905)
  rect 2.5x3.5 smd: 9(0,0)
  silkscreen extent -2.67,-2.55 2.05,3.2
HDR-TH_2P-P2.54-V-M [mm]
  rect 2x2 hole 1.2: 1(-1.27,0)
  round 2 hole 1.2: 2(1.27,0)
  silkscreen extent -2.54,-1.27 2.54,1.27
IND-SMD_L10.8-W10.0_SLO1040H [mil]
  rect 115.1x134.6 smd: 1(188.1,0) 2(-188.1,0)
  silkscreen extent -216,-200 216,200
L0603 [mm]
  rect 0.8x0.864 smd: 1(-0.7,0) 2(0.7,0)
  silkscreen extent -1.42,-0.65 1.42,0.65
LED-SMD_L1.7-W0.6-RD [mm]
  rect 0.8x0.7 smd: 1(-0.9,0) 2(0.9,0)
  silkscreen extent -0.59,-0.32 0.61,0.8
LQFP-64_L10.0-W10.0-P0.50-LS12.0-BL [mm]
  oval 0.3x2 smd: 1(-3.75,-5.75) 2(-3.25,-5.75) 3(-2.75,-5.75) 4(-2.25,-5.75) 5(-1.75,-5.75) 6(-1.25,-5.75) 7(-0.75,-5.75) 8(-0.25,-5.75) 9(0.25,-5.75) 10(0.75,-5.75) 11(1.25,-5.75) 12(1.75,-5.75) 13(2.25,-5.75) 14(2.75,-5.75) 15(3.25,-5.75) 16(3.75,-5.75) 33(3.75,5.75) 34(3.25,5.75) 35(2.75,5.75) 36(2.25,5.75) 37(1.75,5.75) 38(1.25,5.75) 39(0.75,5.75) 40(0.25,5.75) 41(-0.25,5.75) 42(-0.75,5.75) 43(-1.25,5.75) 44(-1.75,5.75) 45(-2.25,5.75) 46(-2.75,5.75) 47(-3.25,5.75) 48(-3.75,5.75)
  oval 2x0.3 smd: 17(5.75,-3.75) 18(5.75,-3.25) 19(5.75,-2.75) 20(5.75,-2.25) 21(5.75,-1.75) 22(5.75,-1.25) 23(5.75,-0.75) 24(5.75,-0.25) 25(5.75,0.25) 26(5.75,0.75) 27(5.75,1.25) 28(5.75,1.75) 29(5.75,2.25) 30(5.75,2.75) 31(5.75,3.25) 32(5.75,3.75) 49(-5.75,3.75) 50(-5.75,3.25) 51(-5.75,2.75) 52(-5.75,2.25) 53(-5.75,1.75) 54(-5.75,1.25) 55(-5.75,0.75) 56(-5.75,0.25) 57(-5.75,-0.25) 58(-5.75,-0.75) 59(-5.75,-1.25) 60(-5.75,-1.75) 61(-5.75,-2.25) 62(-5.75,-2.75) 63(-5.75,-3.25) 64(-5.75,-3.75)
  silkscreen extent -5,-5.79 5,5
MICRO-USB-SMD_ZX62-AB-5PA [mm]
  rect 0.4x1.35 smd: 1(-1.3,1.337) 2(-0.65,1.337) 3(0,1.337) 4(0.65,1.337) 5(1.3,1.337)
  rect 1.8x1.9 smd: 6(-4,-1.337) 6(4,-1.337)
  rect 2.1x1.35 smd: 6(-3.1,1.337) 6(3.1,1.337)
  rect 1.9x1.9 smd: 6(-1.2,-1.337) 6(1.2,-1.337)
  Board Outline Layer lines w0.254: -4.2,-3.3 -4.2,-4.1 -4.2,-3.3 ; -4.2,-3.3 4.2,-3.3 ; -4.2,-3.3 4.2,-3.3 ; 4.2,-3.3 4.2,-4.2 4.2,-3.3
  silkscreen extent -4.22,-4.1 4.16,1.66
R0603 [mil]
  rect 31.75x34.02 smd: 1(-29.66,0) 2(29.66,0)
  silkscreen extent -55,-26 55,26
R0805 [mm]
  rect 1.133x1.377 smd: 1(-1,0) 2(1,0)
  silkscreen extent -1.76,-0.92 1.76,0.92
R1206 [mil]
  rect 47.54x66.97 smd: 1(-58.22,0) 2(58.22,0)
  silkscreen extent -91,-42 91,42
R2512 [mil]
  rect 50.49x136.06 smd: 1(-120.72,0) 2(120.72,0)
  silkscreen extent -155,-77 155,77
SMA_L4.3-W2.6-LS5.2-RD [mm]
  rect 2x2 smd: 1(-2.2,0) 2(2.2,0)
  silkscreen extent -2.98,-1.5 2.6,1.5
SOD-123FL_L3.0-W1.9-LS3.7-FD [mm]
  rect 1.208x1.33 smd: 1(-1.624,0) 2(1.624,0)
  silkscreen extent -1.58,-1.08 1.85,1.08
SOT-23-5_L3.0-W1.7-P0.95-LS2.8-TL [mm]
  rect 1x0.55 smd: 1(-1.271,0.95) 2(-1.271,0) 3(-1.271,-0.95) 4(1.271,-0.95) 5(1.271,0.95)
  silkscreen extent -1.52,-1.52 0.97,1.78
SW-SMD_L3.9-W3.0-P4.45 [mm]
  rect 1.23x1.36 smd: 1(-2.185,0) 2(2.185,0)
  silkscreen extent -2.03,-1.62 2.25,1.62
TEST-TH_BD2.54-P1.4_BLACK [mm]
  round 1.9 hole 1.39: 1(0,0)
  silkscreen extent -1.27,-1.27 1.27,1.27
TH_2P-XT60PW-F [mm]
  oval 1.3x2.2 hole 0.6 slot 1.5 at 90 deg: 1(-6.75,3) 2(6.75,3)
  round 3.8 hole 2.8: 3(-3.6,-3) 4(3.6,-3)
  silkscreen extent -7.75,-4.75 7.75,12.52
VQFN-48_L7.0-W7.0-P0.50-TL-EP5.1 [mm]
  rect 0.665x0.28 smd: 1(-3.407,2.75) 2(-3.407,2.25) 3(-3.407,1.75) 4(-3.407,1.25) 5(-3.407,0.75) 6(-3.407,0.25) 7(-3.407,-0.25) 8(-3.407,-0.75) 9(-3.407,-1.25) 10(-3.407,-1.75) 11(-3.407,-2.25) 12(-3.407,-2.75) 25(3.407,-2.75) 26(3.407,-2.25) 27(3.407,-1.75) 28(3.407,-1.25) 29(3.407,-0.75) 30(3.407,-0.25) 31(3.407,0.25) 32(3.407,0.75) 33(3.407,1.25) 34(3.407,1.75) 35(3.407,2.25) 36(3.407,2.75)
  rect 0.28x0.665 smd: 13(-2.75,-3.407) 14(-2.25,-3.407) 15(-1.75,-3.407) 16(-1.25,-3.407) 17(-0.75,-3.407) 18(-0.25,-3.407) 19(0.25,-3.407) 20(0.75,-3.407) 21(1.25,-3.407) 22(1.75,-3.407) 23(2.25,-3.407) 24(2.75,-3.407) 37(2.75,3.407) 38(2.25,3.407) 39(1.75,3.407) 40(1.25,3.407) 41(0.75,3.407) 42(0.25,3.407) 43(-0.25,3.407) 44(-0.75,3.407) 45(-1.25,3.407) 46(-1.75,3.407) 47(-2.25,3.407) 48(-2.75,3.407)
  rect 5.15x5.15 smd: 49(0,0)
  silkscreen extent -4.11,-3.58 3.58,3.58
VSON-CLIP-8_L5.0-W6.0-P1.27-BL [mm]
  rect 0.7x1.27 smd: 1(-1.904,-3) 2(-0.636,-3) 3(0.636,-3) 4(1.906,-3)
  rect 0.7x1 smd: 5(1.904,3) 6(0.634,3) 7(-0.636,3) 8(-1.906,3)
  rect 4.9x4.5 smd: 8(-0.001,0.39)
  silkscreen extent -2.75,-3.57 2.6,3
VSSOP-8_L2.4-W2.1-P0.50-LS3.2-BR [mm]
  oval 0.75x0.25 smd: 1(1.55,-0.75) 2(1.55,-0.25) 3(1.55,0.25) 4(1.55,0.75) 5(-1.55,0.75) 6(-1.55,0.25) 7(-1.55,-0.25) 8(-1.55,-0.75)
  silkscreen extent -0.9,-1.02 0.9,1

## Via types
v1: diameter 24.02, hole 12.01, Top Layer to Bottom Layer, 707 vias
v2: diameter 236.22, hole 165.35, Top Layer to Bottom Layer, 4 vias

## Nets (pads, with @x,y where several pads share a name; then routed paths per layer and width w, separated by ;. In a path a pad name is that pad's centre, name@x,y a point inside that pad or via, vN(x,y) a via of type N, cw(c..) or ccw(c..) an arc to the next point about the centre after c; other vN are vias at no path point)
3.3V: C65.1 C69.2 C70.2 C71.2 C72.2 C73.2 CN2.1 CN5.1 CN6.4 D3.1 L4.1 R90.2 R91.2 R92.2 R94.2 R97.2 R98.2 R99.2 R106.2 R107.2 R108.2 U7.5 U11.1 U11.16 U11.32 U11.48 U11.64 U13.3 U13.6 | length 1558.2
  Top Layer w10: v1(4715,3506.41) R99.2@4764.66,3506.41 ; v1(5180,3883.97) C72.2@5225,3883.97 5225.2,3883.77 U11.48@5303.63,3883.77 ; C73.2@5288.8,4358.97 5290,4357.77 v1(5290,4326.41) 5310,4306.41 5375,4306.41 5382.36,4299.05 U11.32@5382.36,4257.78 ; U11.64@5677.64,3805.04 5677.64,3761.33 5719.57,3719.4 v1(5795,3719.4) ; U11.1@5756.37,3883.77 5777.64,3883.77 5832.64,3828.77 v1(5847.44,3828.77) ; U11.16@5756.37,4179.05 5792.64,4179.05 5819.34,4205.75 C71.2@5819.34,4239.88 5820,4240.54 v1(5820,4296.41) ; v1(5925,3306.07) R97.2@5985,3306.07 ; R97.2@6000,3306.07 6000.18,3306.25 U13.6@6085.32,3306.25 U13.3@6207.36,3306.25
  Top Layer w21.65: C65.1@7800.35,3459.01 U7.5@7864.94,3459.01
  Top Layer w31.73: C73.2@5288.8,4358.97 5356.21,4358.97 L4.1@5356.35,4358.83
  Top Layer w39.37: D3.1@7685,3457.43 7798.78,3457.43 C65.1@7800,3458.65
  Bottom Layer w10: v1(4940,3390.78) 5024.71,3390.78 R108.2@5025.34,3391.41 ; v1(5516.3,3436.41) 5565.89,3436.41 R92.2@5570.26,3440.78 ; R91.2@5700,3440.78 v1(5700,3486.41) ; R90.2@5832.63,3440.78 v1(5880,3440.78)
  other v1: 7340,3421.41 5347.63,3440.78 5215,3442.42 7340,3458.91 7340,3496.41 6235,3881.86 5647.53,4486.73
5V: C64.1 CN1.1 CN4.1 CN7.4 L3.1 LED5.2 R73.2 R75.2 U7.1 U12.1 U13.7 U15.1 | length 168.1
  Top Layer w10: v1(6027.42,3273.99) 6040,3286.57 U13.7@6085.32,3286.57 ; U7.1@7965.06,3459.01 8070,3459.01
  other v1: 8133.9,3355.31 8429.17,3374.99 8389.8,3375.62 8133.9,3414.36 8192.95,3414.36 8311.06,3414.36 8350.43,3414.36 8389.8,3414.36 8429.17,3414.36 8232.32,3453.73 8271.69,3453.73 8311.06,3453.73 8232.32,3493.1 8271.69,3493.1 8311.06,3493.1
$1I2936\$1N44875: C20.1 U1.5 | length 212.2
  Top Layer w10: U1.5@6847.67,4086.47 6904.94,4086.47 6966.56,4024.85 C20.1@7034.37,4024.85
$1I2936\$1N44882: C19.1 U1.4 | length 137.5
  Top Layer w10: U1.4@6847.67,4066.79 6882.19,4066.79 C19.1@6955,3993.97
$1I2936\$1N44883: C19.2 U1.3 | length 168.3
  Top Layer w10: U1.3@6847.67,4047.1 6848.35,4046.41 6875,4046.41 6895,4026.41 6895,3998.85 C19.2@6955,3938.85
$1I2936\$1N44900: C28.2 Q1.4 R1.1 | length 156.3
  Bottom Layer w10: Q1.4@6333.63,5438.89 C28.2@6403.85,5438.89
  Bottom Layer w23.62: Q1.4@6333.63,5438.89 6334.37,5438.16 R1.1@6334.37,5353.07
$1I2936\$1N44903: C29.2 Q2.4 R2.2 | length 153.1
  Bottom Layer w10: Q2.4@6333.63,5753.89 6403.33,5753.89 C29.2@6403.85,5753.38
  Bottom Layer w23.62: R2.2@6333.11,5671.41 6333.63,5671.93 Q2.4@6333.63,5753.89
$1I2936\$1N44906: Q7.4 R7.1 | length 95.9
  Bottom Layer w23.62: R7.1@6096.46,5353.07 6096.71,5352.82 Q7.4@6096.71,5257.29
$1I2936\$1N44907: Q8.4 R8.2 | length 81.9
  Bottom Layer w23.62: R8.2@6094.01,5028.07 6096.71,5025.36 Q8.4@6096.71,4947.29
$1I2936\$1N44911: C30.2 Q5.4 R5.1 | length 161.2
  Bottom Layer w10: Q5.4@7948.63,5448.89 C30.2@8023.69,5448.89
  Bottom Layer w23.62: Q5.4@7948.63,5448.89 7949.37,5448.16 R5.1@7949.37,5363.07
$1I2936\$1N44914: C31.2 Q6.4 R6.2 | length 157.8
  Bottom Layer w10: Q6.4@7948.63,5763.89 8023.61,5763.89 C31.2@8023.68,5763.97
  Bottom Layer w23.62: R6.2@7948.11,5681.41 7948.63,5681.93 Q6.4@7948.63,5763.89
$1I2936\$1N44917: Q11.4 R11.1 | length 95.9
  Bottom Layer w23.62: R11.1@7711.46,5363.07 7711.71,5362.82 Q11.4@7711.71,5267.29
$1I2936\$1N44918: Q12.4 R12.2 | length 81.9
  Bottom Layer w23.62: R12.2@7709.01,5038.07 7711.71,5035.36 Q12.4@7711.71,4957.29
$1I2936\$1N44964: C26.2 Q3.4 R3.1 | length 159.2
  Bottom Layer w10: Q3.4@7142.04,5443.76 7214.79,5443.76 C26.2@7215,5443.97
  Bottom Layer w23.62: Q3.4@7142.04,5443.76 7142.77,5443.03 R3.1@7142.77,5357.94
$1I2936\$1N44967: C27.2 Q4.4 R4.2 | length 155.7
  Bottom Layer w10: Q4.4@7142.04,5758.76 C27.2@7215,5758.76
  Bottom Layer w23.62: R4.2@7141.51,5676.28 7142.04,5676.8 Q4.4@7142.04,5758.76
$1I2936\$1N44970: Q9.4 R9.1 | length 95.9
  Bottom Layer w23.62: R9.1@6904.86,5357.94 6905.12,5357.68 Q9.4@6905.12,5262.16
$1I2936\$1N44971: Q10.4 R10.2 | length 81.9
  Bottom Layer w23.62: R10.2@6902.41,5032.94 6905.12,5030.23 Q10.4@6905.12,4952.16
$1I2936\$1N44985: LED1.1 R21.2 | length 66.6
  Top Layer w10: LED1.1@6143.6,3623.17 6209.12,3623.17 R21.2@6209.89,3623.95
$1I2936\$1N44986: LED2.1 R22.2 | length 64.4
  Top Layer w10: LED2.1@6282.12,3621.01 6282.89,3621.79 R22.2@6346.17,3621.79
$1I2936\A_H: C9.1 Q11.1 Q11.2 Q11.3 Q12.1 Q12.2 Q12.3 R15.2 U1.11 | length 1255.7
  Top Layer w10: U1.11@6847.67,4204.58 6868.16,4204.58 v1(6925,4261.41)
  Top Layer w23.62: R15.2@7524.28,4871.41 7521.68,4868.81 7521.68,4655.44 7606.68,4570.44 v1(7610.61,4570.44)
  Inner1 w10: v1(6925,4261.41) 7234.03,4570.44 v1(7610.61,4570.44)
  other v1: 7600.75,4871.92 7640.12,4871.92 7600.75,4911.29 7640.12,4911.29 7561.38,4950.66 7600.75,4950.66 7640.12,4950.66
$1I2936\B_H: C8.1 Q9.1 Q9.2 Q9.3 Q10.1 Q10.2 Q10.3 R14.2 U1.14 | length 673.9
  Top Layer w10: U1.14@6802.1,4250.15 6802.1,4279.03 v1(6829.6,4306.53)
  Top Layer w23.62: R14.2@6717.68,4866.28 6717.68,4653.75 v1(6797.36,4574.07)
  Inner1 w10: v1(6797.36,4574.07) 6829.6,4541.83 v1(6829.6,4306.53)
  other v1: 6785.75,4836.29 6825.12,4836.29 6785.75,4875.66 6825.12,4875.66 6785.75,4915.03 6825.12,4915.03 6785.75,4954.4 6825.12,4954.4
$1I2936\C_H: C7.1 Q7.1 Q7.2 Q7.3 Q8.1 Q8.2 Q8.3 R13.2 U1.21 | length 1190.9
  Top Layer w10: v1(6655.86,4311.53) 6664.31,4303.07 U1.21@6664.31,4250.15
  Top Layer w23.62: R13.2@5909.28,4861.41 5906.68,4858.81 5906.68,4645.44 5991.68,4560.44 v1(5995.61,4560.44)
  Inner1 w10: v1(5995.61,4560.44) 6021.58,4586.41 6380.97,4586.41 v1(6655.86,4311.53)
  other v1: 5985.75,4861.92 6025.12,4861.92 5985.75,4901.29 6025.12,4901.29 5946.38,4940.66 5985.75,4940.66 6025.12,4940.66
$1I2936\DVDD: C13.2 C15.2 R16.2 U1.26 U1.36 | length 544
  Top Layer w10: U1.36@6579.37,4007.73 6543.36,4007.73 6517.05,3981.41 C15.2@6439.84,3981.41 6412.98,4008.27 6412.98,4070.02 R16.2@6380.52,4102.48 6380.52,4104.05 C13.2@6439.84,4163.37 6439.84,4173.37 6471.04,4204.58 U1.26@6579.37,4204.58
$1I2936\GH_A: R5.2 R6.1 R37.2 U1.8 | length 2459.7
  Top Layer w10: U1.8@6847.67,4145.53 6914.11,4145.53 v1(6950,4181.41)
  Inner1 w10: v1(6950,4181.41) 7250,4481.41 7875,4481.41 7985,4591.41 7985,5246.41 v1(7870,5361.41) v1(7870,5681.41)
  other v1: 7985.63,4646.41
$1I2936\GH_B: R3.2 R4.1 R34.2 U1.17 | length 1559.6
  Top Layer w10: U1.17@6743.05,4250.15 v1(6743.05,4361.41)
  Inner1 w10: v1(7065,5356.41) v1(7065,5676.41)
  Inner2 w10: v1(6743.05,4361.41) 6835,4453.36 v1(6835,4656.41) 7065,4886.41 v1(7065,5356.41)
$1I2936\GH_C: R1.2 R2.1 R33.2 U1.18 | length 1610.3
  Top Layer w10: v1(6693.31,4377.81) 6723.36,4347.77 U1.18@6723.36,4250.15
  Inner1 w10: v1(6255,5666.41) v1(6255,5351.41) 6255,4816.12 v1(6693.31,4377.81)
  other v1: 6427.97,4642.44
$1I2936\GL_A: R11.2 R12.1 R36.2 U1.10 | length 1973.5
  Top Layer w10: U1.10@6847.67,4184.9 6883.48,4184.9 v1(6920,4221.41)
  Inner1 w10: v1(6920,4221.41) 7225,4526.41 7790,4526.41 7845,4581.41 v1(7845,4649) 7845,4981.41 v1(7785,5041.41) 7785,5361.41 v1(7790,5366.41)
$1I2936\GL_B: R9.2 R10.1 R35.2 U1.15 | length 1322.5
  Top Layer w10: U1.15@6782.42,4250.15 6782.42,4295.6 v1(6799.6,4312.78)
  Inner1 w10: v1(6799.6,4312.78) 6799.6,4441.81 6655,4586.41 v1(6655,4641.41) 6685,4641.41 6985,4941.41 v1(6985,5031.41) v1(6985,5351.41)
$1I2936\GL_C: R7.2 R8.1 R32.2 U1.20 | length 1313
  Top Layer w10: v1(6657.74,4342.16) 6683.99,4315.91 U1.20@6683.99,4250.15
  Inner1 w10: v1(6172.75,5351.41) v1(6172.75,5028.07) 6172.75,4828.7 v1(6360.24,4641.22) 6360.24,4639.66 v1(6657.74,4342.16)
$1I3034\$1N44875: C17.1 U2.5 | length 209.6
  Top Layer w10: U2.5@4375.89,4086.47 4449.94,4086.47 4511.56,4024.85 C17.1@4560,4024.85
$1I3034\$1N44882: C16.1 U2.4 | length 109.8
  Top Layer w10: U2.4@4375.89,4066.79 4401.67,4066.79 C16.1@4461.07,4007.39
$1I3034\$1N44883: C16.2 U2.3 | length 157.2
  Top Layer w10: U2.3@4375.89,4047.1 4390.35,4047.1 4417.37,4020.07 4417.37,3967.09 4434.25,3950.21 4459,3950.21 C16.2@4461.07,3952.27
$1I3034\$1N44900: C41.2 Q13.4 R31.1 | length 156.3
  Bottom Layer w10: Q13.4@3843.81,5438.89 C41.2@3914.03,5438.89
  Bottom Layer w23.62: Q13.4@3843.81,5438.89 3844.55,5438.16 R31.1@3844.55,5353.07
$1I3034\$1N44903: C42.2 Q14.4 R38.2 | length 153.1
  Bottom Layer w10: Q14.4@3843.81,5753.89 3913.51,5753.89 C42.2@3914.03,5753.38
  Bottom Layer w23.62: R38.2@3843.29,5671.41 3843.81,5671.93 Q14.4@3843.81,5753.89
$1I3034\$1N44906: Q15.4 R43.1 | length 95.9
  Bottom Layer w23.62: R43.1@3606.64,5353.07 3606.89,5352.82 Q15.4@3606.89,5257.29
$1I3034\$1N44907: Q16.4 R44.2 | length 81.9
  Bottom Layer w23.62: R44.2@3604.18,5028.07 3606.89,5025.36 Q16.4@3606.89,4947.29
$1I3034\$1N44911: C43.2 Q17.4 R41.1 | length 161.2
  Bottom Layer w10: Q17.4@5458.81,5448.89 C43.2@5533.86,5448.89
  Bottom Layer w23.62: Q17.4@5458.81,5448.89 5459.55,5448.16 R41.1@5459.55,5363.07
$1I3034\$1N44914: C44.2 Q18.4 R42.2 | length 157.8
  Bottom Layer w10: Q18.4@5458.81,5763.89 5533.78,5763.89 C44.2@5533.86,5763.97
  Bottom Layer w23.62: R42.2@5458.29,5681.41 5458.81,5681.93 Q18.4@5458.81,5763.89
$1I3034\$1N44917: Q19.4 R47.1 | length 95.9
  Bottom Layer w23.62: R47.1@5221.64,5363.07 5221.89,5362.82 Q19.4@5221.89,5267.29
$1I3034\$1N44918: Q20.4 R48.2 | length 81.9
  Bottom Layer w23.62: R48.2@5219.18,5038.07 5221.89,5035.36 Q20.4@5221.89,4957.29
$1I3034\$1N44964: C39.2 Q21.4 R39.1 | length 159.2
  Bottom Layer w10: Q21.4@4652.21,5443.76 4724.97,5443.76 C39.2@4725.18,5443.97
  Bottom Layer w23.62: Q21.4@4652.21,5443.76 4652.95,5443.03 R39.1@4652.95,5357.94
$1I3034\$1N44967: C40.2 Q22.4 R40.2 | length 155.7
  Bottom Layer w10: Q22.4@4652.21,5758.76 C40.2@4725.18,5758.76
  Bottom Layer w23.62: R40.2@4651.69,5676.28 4652.21,5676.8 Q22.4@4652.21,5758.76
$1I3034\$1N44970: Q23.4 R45.1 | length 95.9
  Bottom Layer w23.62: R45.1@4415.04,5357.94 4415.29,5357.68 Q23.4@4415.29,5262.16
$1I3034\$1N44971: Q24.4 R46.2 | length 81.9
  Bottom Layer w23.62: R46.2@4412.59,5032.94 4415.29,5030.23 Q24.4@4415.29,4952.16
$1I3034\$1N44985: LED3.1 R19.2 | length 53.1
  Top Layer w10: LED3.1@3626.03,4165.21 3626.12,4165.12 R19.2@3626.12,4112.17
$1I3034\$1N44986: LED4.1 R20.2 | length 48.1
  Top Layer w10: LED4.1@3622.01,4040.21 3622.1,4040.12 R20.2@3622.1,3992.17
$1I3034\A_H: C32.1 Q19.1 Q19.2 Q19.3 Q20.1 Q20.2 Q20.3 R18.2 U2.11 | length 1261
  Top Layer w10: U2.11@4375.89,4204.58 4396.38,4204.58 v1(4453.21,4261.41)
  Top Layer w23.62: R18.2@5034.46,4871.41 5034.46,4670.87 5134.89,4570.44 v1(5138.82,4570.44)
  Inner1 w10: v1(4453.21,4261.41) 4762.24,4570.44 v1(5138.82,4570.44)
  other v1: 5110.92,4871.92 5150.29,4871.92 5110.92,4911.29 5150.29,4911.29 5110.92,4950.66 5150.29,4950.66
$1I3034\B_H: C36.1 Q23.1 Q23.2 Q23.3 Q24.1 Q24.2 Q24.3 R23.2 U2.14 | length 685.5
  Top Layer w10: U2.14@4330.32,4250.15 4330.31,4279.03 v1(4357.81,4306.53)
  Top Layer w23.62: R23.2@4227.86,4866.28 4227.1,4865.52 4227.1,4671.64 4325.17,4573.57 v1(4326.16,4573.57)
  Inner1 w10: v1(4326.16,4573.57) 4331.16,4573.57 4357.81,4546.92 v1(4357.81,4306.53)
  other v1: 4295.92,4836.29 4335.29,4836.29 4295.92,4875.66 4335.29,4875.66 4295.92,4915.03 4335.29,4915.03 4295.92,4954.4 4335.29,4954.4
$1I3034\C_H: C23.1 Q15.1 Q15.2 Q15.3 Q16.1 Q16.2 Q16.3 R17.2 U2.21 | length 1191.5
  Top Layer w10: v1(4184.07,4311.53) 4192.52,4303.07 U2.21@4192.53,4250.15
  Top Layer w23.62: R17.2@3419.46,4861.41 3419.46,4664.81 v1(3523.82,4560.44)
  Inner1 w10: v1(3523.82,4560.44) 3546.81,4583.43 3912.16,4583.43 v1(4184.07,4311.53)
  other v1: 3470,4832.36 3509.37,4832.36 3470,4871.73 3509.37,4871.73 3470,4911.1 3509.37,4911.1 3470,4950.47 3509.37,4950.47
$1I3034\DVDD: C12.2 C14.2 R49.2 U2.26 U2.36 | length 546.4
  Top Layer w10: U2.36@4109.37,4007.73 4093.13,4007.73 4083.13,4017.73 4058.36,4017.73 4032.05,3991.41 3979.84,3991.41 3969.84,3981.41 3940,4011.25 3940,4073 3910.52,4102.48 3910.52,4104.05 4011.04,4204.58 U2.26@4109.37,4204.58
$1I3034\GH_A: R30.2 R41.2 R42.1 U2.8 | length 2380.9
  Top Layer w10: U2.8@4375.89,4145.53 4442.33,4145.53 v1(4478.21,4181.41)
  Inner1 w10: v1(4478.21,4181.41) 4793.21,4496.41 5325,4496.41 5475,4646.41 v1(5475,4661.41) 5475,5266.59 v1(5380.18,5361.41) v1(5380.18,5681.41)
$1I3034\GH_B: R27.2 R39.2 R40.1 U2.17 | length 1571.4
  Top Layer w10: U2.17@4271.27,4250.15 4271.26,4274 4272.2,4274.94 4272.2,4345.98 v1(4274.07,4347.85)
  Inner1 w10: v1(4415,4481.41) 4593.21,4659.62 v1(4593.21,4661.41) 4593.21,5338.37 v1(4575.18,5356.41) v1(4575.18,5676.41)
  Inner2 w10: v1(4274.07,4347.85) 4407.63,4481.41 v1(4415,4481.41)
$1I3034\GH_C: R26.2 R31.2 R38.1 U2.18 | length 1649.1
  Top Layer w10: v1(4221.52,4377.81) 4246.08,4353.26 4246.08,4318.41 4251.57,4312.91 U2.18@4251.58,4250.15
  Inner1 w10: v1(3765.18,5666.41) v1(3765.18,5351.41) 3765.18,4816.12 3923.86,4657.44 v1(3977.36,4657.44) 4221.52,4413.28 v1(4221.52,4377.81)
$1I3034\GL_A: R29.2 R47.2 R48.1 U2.10 | length 1950.8
  Top Layer w10: U2.10@4375.89,4184.9 4411.7,4184.9 v1(4448.21,4221.41)
  Inner1 w10: v1(4448.21,4221.41) 4748.21,4521.41 5245,4521.41 v1(5385,4661.41) 5385,4951.59 v1(5295.18,5041.41) 5295.18,5361.41 v1(5300.18,5366.41)
$1I3034\GL_B: R28.2 R45.2 R46.1 U2.15 | length 1246.3
  Top Layer w10: U2.15@4310.64,4250.15 4310.63,4295.6 v1(4327.81,4312.78)
  Inner1 w10: v1(4327.81,4312.78) 4327.81,4493.6 v1(4245,4576.41) 4495.18,4826.59 v1(4495.18,5031.41) v1(4495.18,5351.41)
